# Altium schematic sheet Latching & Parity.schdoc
size 411 x 357 mm
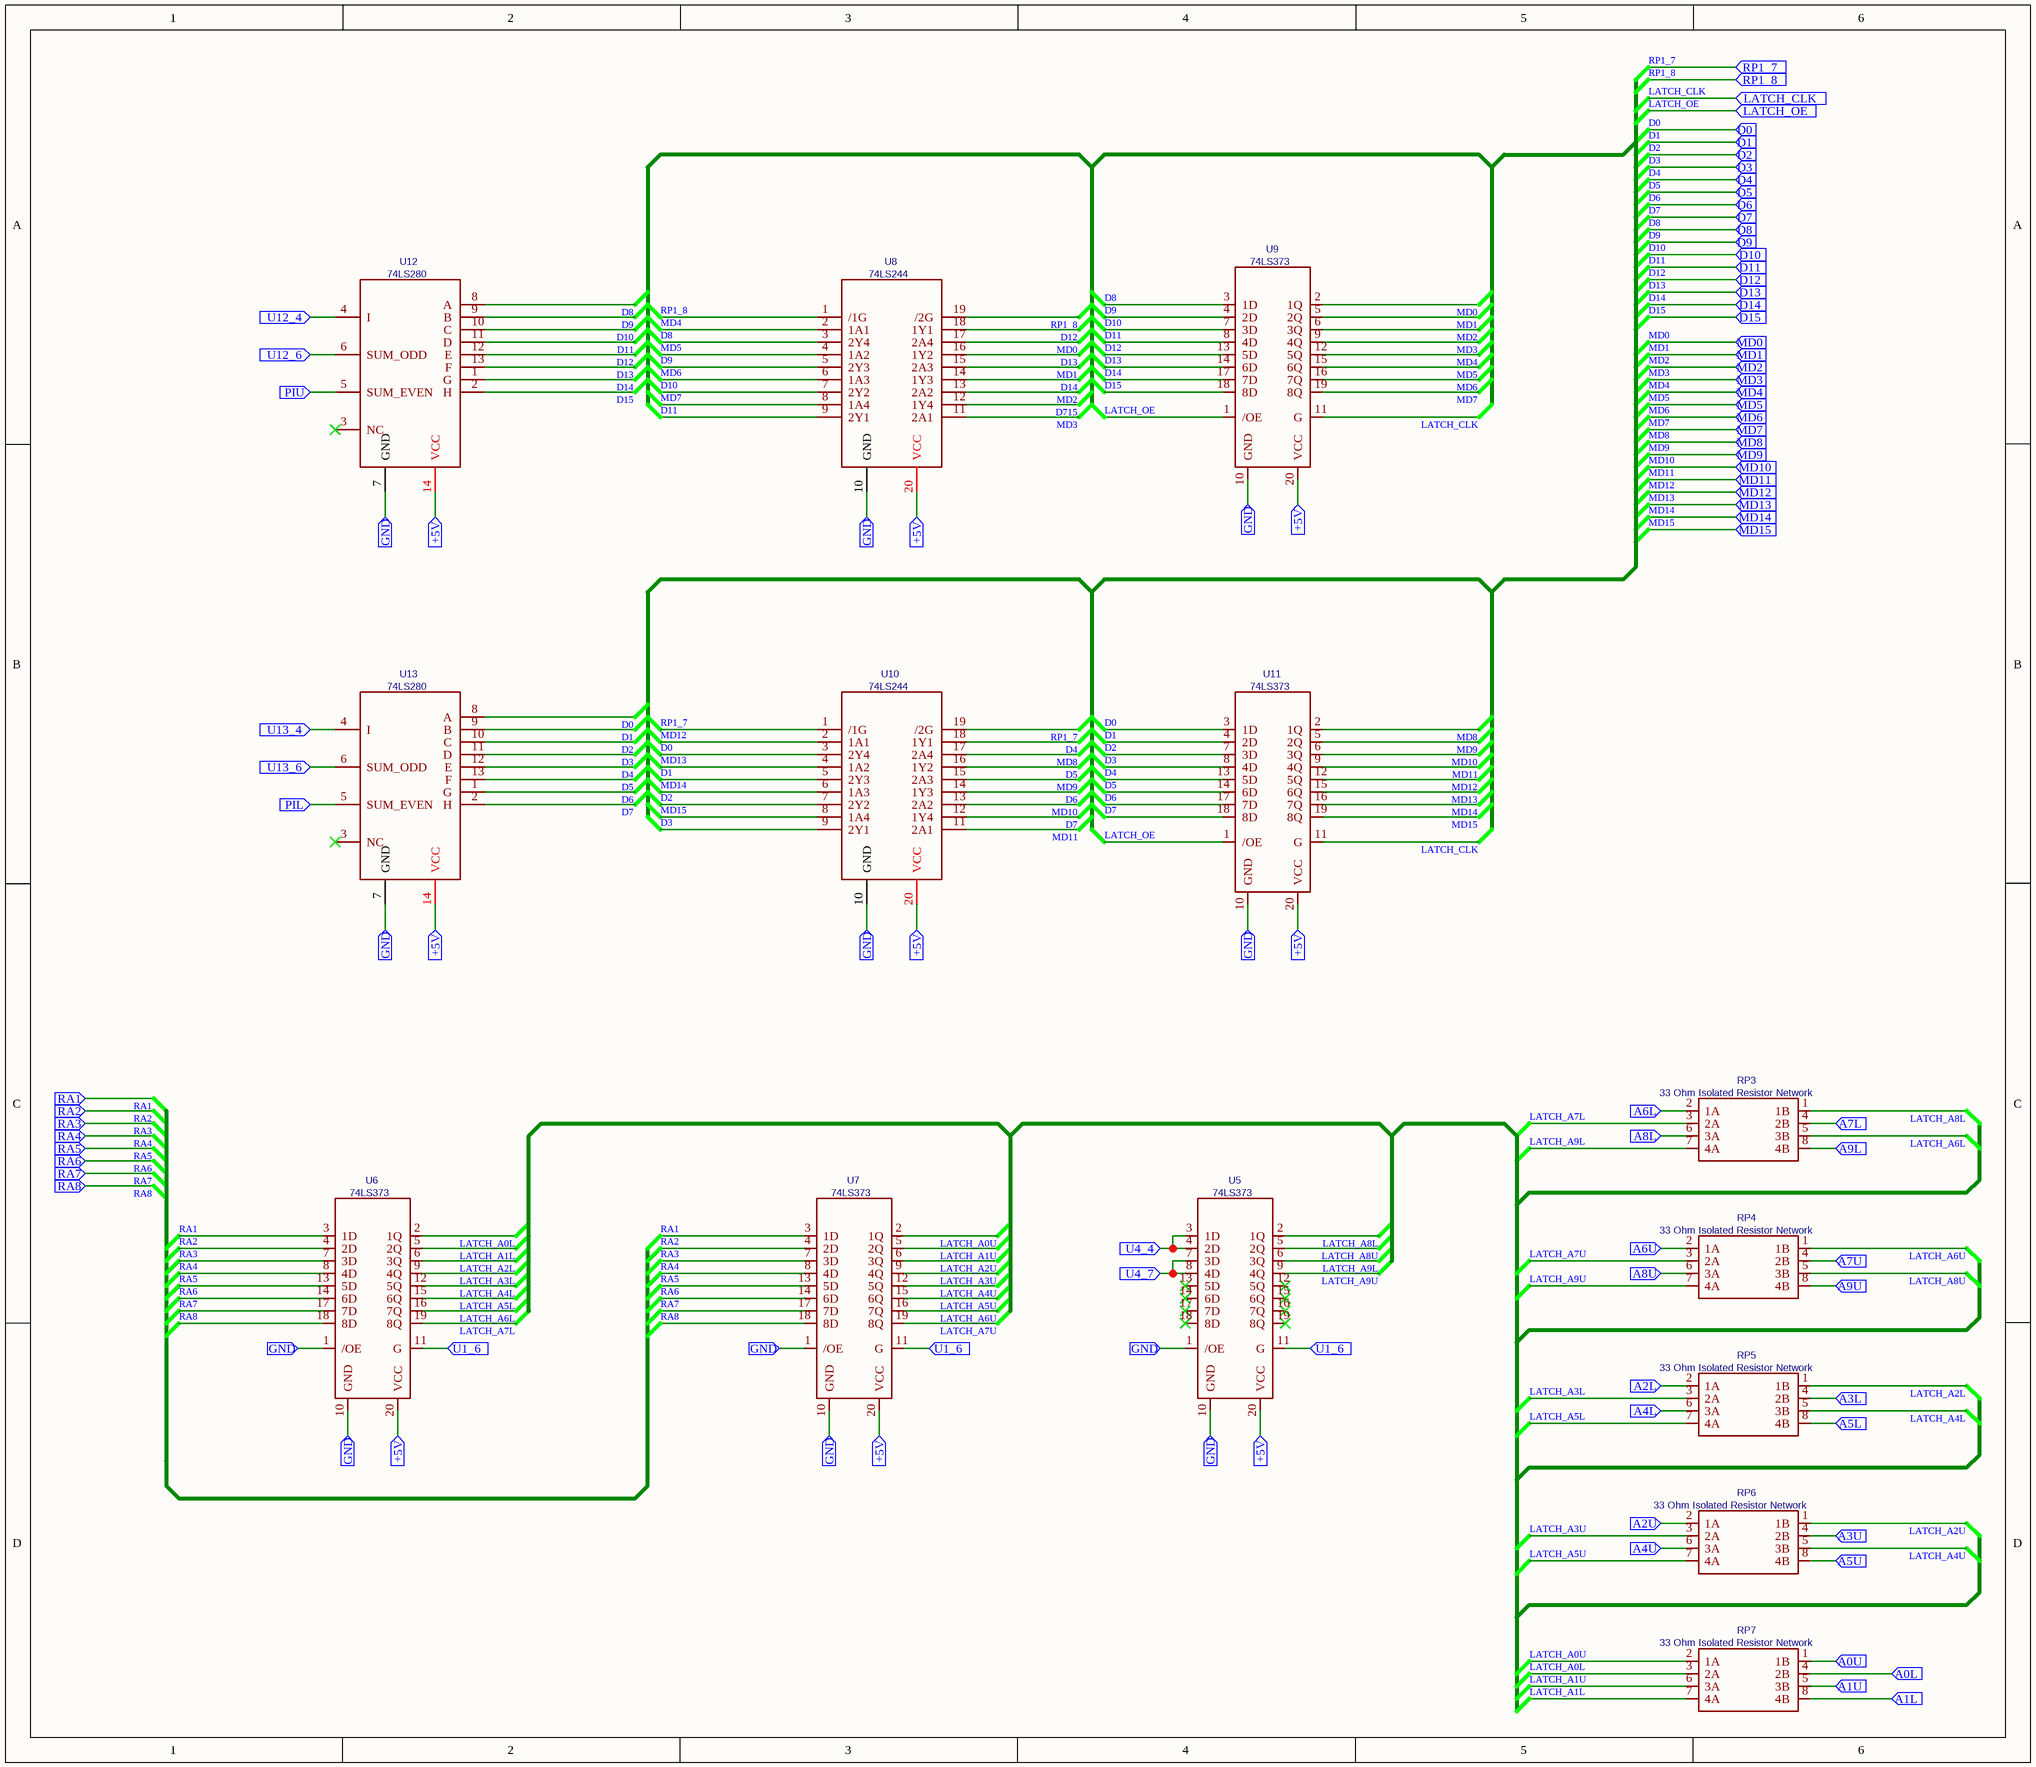
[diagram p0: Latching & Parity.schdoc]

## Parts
RP3  33 Ohm Isolated Resistor Network  [RES_PACK_LINE]
RP4  33 Ohm Isolated Resistor Network  [RES_PACK_LINE]
RP5  33 Ohm Isolated Resistor Network  [RES_PACK_LINE]
RP6  33 Ohm Isolated Resistor Network  [RES_PACK_LINE]
RP7  33 Ohm Isolated Resistor Network  [RES_PACK_LINE]
U5  74LS373  [DIP20_LISA]
U6  74LS373  [DIP20_LISA]
U7  74LS373  [DIP20_LISA]
U8  74LS244  [DIP20_LISA]
U9  74LS373  [DIP20_LISA]
U10  74LS244  [DIP20_LISA]
U11  74LS373  [DIP20_LISA]
U12  74LS280  [DIP-14_L19.4-W6.4-P2.54-LS7.6-BL]
U13  74LS280  [DIP-14_L19.4-W6.4-P2.54-LS7.6-BL]

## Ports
+5V (in), A0L (in), A0U (in), A1L (in), A1U (in), A2L (in), A2U (in), A3L (in), A3U (in), A4L (in), A4U (in), A5L (in), A5U (in), A6L (in), A6U (in), A7L (in), A7U (in), A8L (in), A8U (in), A9L (in), A9U (in), D0 (in), D1 (in), D2 (in), D3 (in), D4 (in), D5 (in), D6 (in), D7 (in), D8 (in), D9 (in), D10 (in), D11 (in), D12 (in), D13 (in), D14 (in), D15 (in), GND (in), LATCH_CLK (in), LATCH_OE (in), MD0 (in), MD1 (in), MD2 (in), MD3 (in), MD4 (in), MD5 (in), MD6 (in), MD7 (in), MD8 (in), MD9 (in), MD10 (in), MD11 (in), MD12 (in), MD13 (in), MD14 (in), MD15 (in), PIL (in), PIU (in), RA1 (in), RA2 (in), RA3 (in), RA4 (in), RA5 (in), RA6 (in), RA7 (in), RA8 (in), RP1_7 (in), RP1_8 (in), U1_6 (in), U4_4 (in), U4_7 (in), U12_4 (in), U12_6 (in), U13_4 (in), U13_6 (in)

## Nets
+5V: U5.20(VCC) U6.20(VCC) U7.20(VCC) U8.20(VCC) U9.20(VCC) U10.20(VCC) U11.20(VCC) U12.14(VCC) U13.14(VCC) ; port +5V
A0L: RP7.4(2B) ; port A0L
A0U: RP7.1(1B) ; port A0U
A1L: RP7.8(4B) ; port A1L
A1U: RP7.5(3B) ; port A1U
A2L: RP5.2(1A) ; port A2L
A2U: RP6.2(1A) ; port A2U
A3L: RP5.4(2B) ; port A3L
A3U: RP6.4(2B) ; port A3U
A4L: RP5.6(3A) ; port A4L
A4U: RP6.6(3A) ; port A4U
A5L: RP5.8(4B) ; port A5L
A5U: RP6.8(4B) ; port A5U
A6L: RP3.2(1A) ; port A6L
A6U: RP4.2(1A) ; port A6U
A7L: RP3.4(2B) ; port A7L
A7U: RP4.4(2B) ; port A7U
A8L: RP3.6(3A) ; port A8L
A8U: RP4.6(3A) ; port A8U
A9L: RP3.8(4B) ; port A9L
A9U: RP4.8(4B) ; port A9U
D0: U10.3(2Y4) U11.3(1D) U13.8(A) ; port D0
D1: U10.5(2Y3) U11.4(2D) U13.9(B) ; port D1
D2: U10.7(2Y2) U11.7(3D) U13.10(C) ; port D2
D3: U10.9(2Y1) U11.8(4D) U13.11(D) ; port D3
D4: U10.18(1Y1) U11.13(5D) U13.12(E) ; port D4
D5: U10.16(1Y2) U11.14(6D) U13.13(F) ; port D5
D6: U10.14(1Y3) U11.17(7D) U13.1(G) ; port D6
D7: U10.12(1Y4) U11.18(8D) U13.2(H) ; port D7
D8: U8.3(2Y4) U9.3(1D) U12.8(A) ; port D8
D9: U8.5(2Y3) U9.4(2D) U12.9(B) ; port D9
D10: U8.7(2Y2) U9.7(3D) U12.10(C) ; port D10
D11: U8.9(2Y1) U9.8(4D) U12.11(D) ; port D11
D12: U8.18(1Y1) U9.13(5D) U12.12(E) ; port D12
D13: U8.16(1Y2) U9.14(6D) U12.13(F) ; port D13
D14: U8.14(1Y3) U9.17(7D) U12.1(G) ; port D14
D15: U9.18(8D) U12.2(H) ; port D15
D715: U8.12(1Y4)
GND: U5.1(/OE) U5.10(GND) U6.1(/OE) U6.10(GND) U7.1(/OE) U7.10(GND) U8.10(GND) U9.10(GND) U10.10(GND) U11.10(GND) U12.7(GND) U13.7(GND) ; port GND
LATCH_A0L: RP7.3(2A) U6.2(1Q)
LATCH_A0U: RP7.2(1A) U7.2(1Q)
LATCH_A1L: RP7.7(4A) U6.5(2Q)
LATCH_A1U: RP7.6(3A) U7.5(2Q)
LATCH_A2L: RP5.1(1B) U6.6(3Q)
LATCH_A2U: RP6.1(1B) U7.6(3Q)
LATCH_A3L: RP5.3(2A) U6.9(4Q)
LATCH_A3U: RP6.3(2A) U7.9(4Q)
LATCH_A4L: RP5.5(3B) U6.12(5Q)
LATCH_A4U: RP6.5(3B) U7.12(5Q)
LATCH_A5L: RP5.7(4A) U6.15(6Q)
LATCH_A5U: RP6.7(4A) U7.15(6Q)
LATCH_A6L: RP3.5(3B) U6.16(7Q)
LATCH_A6U: RP4.1(1B) U7.16(7Q)
LATCH_A7L: RP3.3(2A) U6.19(8Q)
LATCH_A7U: RP4.3(2A) U7.19(8Q)
LATCH_A8L: RP3.1(1B) U5.2(1Q)
LATCH_A8U: RP4.5(3B) U5.5(2Q)
LATCH_A9L: RP3.7(4A) U5.6(3Q)
LATCH_A9U: RP4.7(4A) U5.9(4Q)
LATCH_CLK: U9.11(G) U11.11(G) ; port LATCH_CLK
LATCH_OE: U9.1(/OE) U11.1(/OE) ; port LATCH_OE
MD0: U8.17(2A4) U9.2(1Q) ; port MD0
MD1: U8.15(2A3) U9.5(2Q) ; port MD1
MD2: U8.13(2A2) U9.6(3Q) ; port MD2
MD3: U8.11(2A1) U9.9(4Q) ; port MD3
MD4: U8.2(1A1) U9.12(5Q) ; port MD4
MD5: U8.4(1A2) U9.15(6Q) ; port MD5
MD6: U8.6(1A3) U9.16(7Q) ; port MD6
MD7: U8.8(1A4) U9.19(8Q) ; port MD7
MD8: U10.17(2A4) U11.2(1Q) ; port MD8
MD9: U10.15(2A3) U11.5(2Q) ; port MD9
MD10: U10.13(2A2) U11.6(3Q) ; port MD10
MD11: U10.11(2A1) U11.9(4Q) ; port MD11
MD12: U10.2(1A1) U11.12(5Q) ; port MD12
MD13: U10.4(1A2) U11.15(6Q) ; port MD13
MD14: U10.6(1A3) U11.16(7Q) ; port MD14
MD15: U10.8(1A4) U11.19(8Q) ; port MD15
PIL: U13.5(SUM_EVEN) ; port PIL
PIU: U12.5(SUM_EVEN) ; port PIU
RA1: U6.3(1D) U7.3(1D) ; port RA1
RA2: U6.4(2D) U7.4(2D) ; port RA2
RA3: U6.7(3D) U7.7(3D) ; port RA3
RA4: U6.8(4D) U7.8(4D) ; port RA4
RA5: U6.13(5D) U7.13(5D) ; port RA5
RA6: U6.14(6D) U7.14(6D) ; port RA6
RA7: U6.17(7D) U7.17(7D) ; port RA7
RA8: U6.18(8D) U7.18(8D) ; port RA8
RP1_7: U10.1(/1G) U10.19(/2G) ; port RP1_7
RP1_8: U8.1(/1G) U8.19(/2G) ; port RP1_8
U1_6: U5.11(G) U6.11(G) U7.11(G) ; port U1_6
U4_4: U5.3(1D) U5.4(2D) ; port U4_4
U4_7: U5.7(3D) U5.8(4D) ; port U4_7
U12_4: U12.4(I) ; port U12_4
U12_6: U12.6(SUM_ODD) ; port U12_6
U13_4: U13.4(I) ; port U13_4
U13_6: U13.6(SUM_ODD) ; port U13_6

Not connected (* = marked no-connect by the designer): U5 12(5Q)* 13(5D)* 14(6D)* 15(6Q)* 16(7Q)* 17(7D)* 18(8D)* 19(8Q)*; U12 3(NC)*; U13 3(NC)*

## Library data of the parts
RP3-RP7 = 33 Ohm Isolated Resistor Network: Contributor: William Tooker
U5-U7 U9 U11 = 74LS373: Contributor: William Tooker
U8 U10 = 74LS244: Contributor: William Tooker
U12 U13 = 74LS280: Contributor: William Tooker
